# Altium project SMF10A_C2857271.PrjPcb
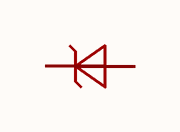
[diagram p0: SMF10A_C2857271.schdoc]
1 sheet, 1 parts. Net scope: global (net labels, ports and power ports of the same name join across sheets).

## Sheet SMF10A_C2857271.schdoc
size 127 x 101 mm

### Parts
D?  smf10a_c2857271  [SOD-123FL_L2.7-W1.8-LS3.7-RD]  (value not drawn)

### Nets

Not connected (* = marked no-connect by the designer): D? 1 2

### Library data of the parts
D? = smf10a_c2857271: 极性:单向;反向截止电压(Vrwm):10V;钳位电压:17V;峰值脉冲电流(Ipp):11.8A;峰值脉冲功率(Ppp):200W@10/1000us;击穿电压(VBR):11.1V;; Manufacturer: JSMSEMI(杰盛微); ManufacturerPart: SMF10A; AddInBom: yes; ModelId: 86f9151e155e4fe2af0c4f2e0a80302e; ModelName: SOD-123FL_L2.8-W1.8-H1.1-LS3.6; ModelTransform: 141.732,70.866,0,180,0,0,0,0,0; Polarity: 单向; Reverse Stand-Off Voltage (Vrwm): 10V; Clamping Voltage: 17V; Peak Pulse Current (Ipp): 11.8A; Voltage - Breakdown: 11.1V; Reverse Leakage Current (Ir): 2.5uA; Number of Channels: 单路; Type: TVS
